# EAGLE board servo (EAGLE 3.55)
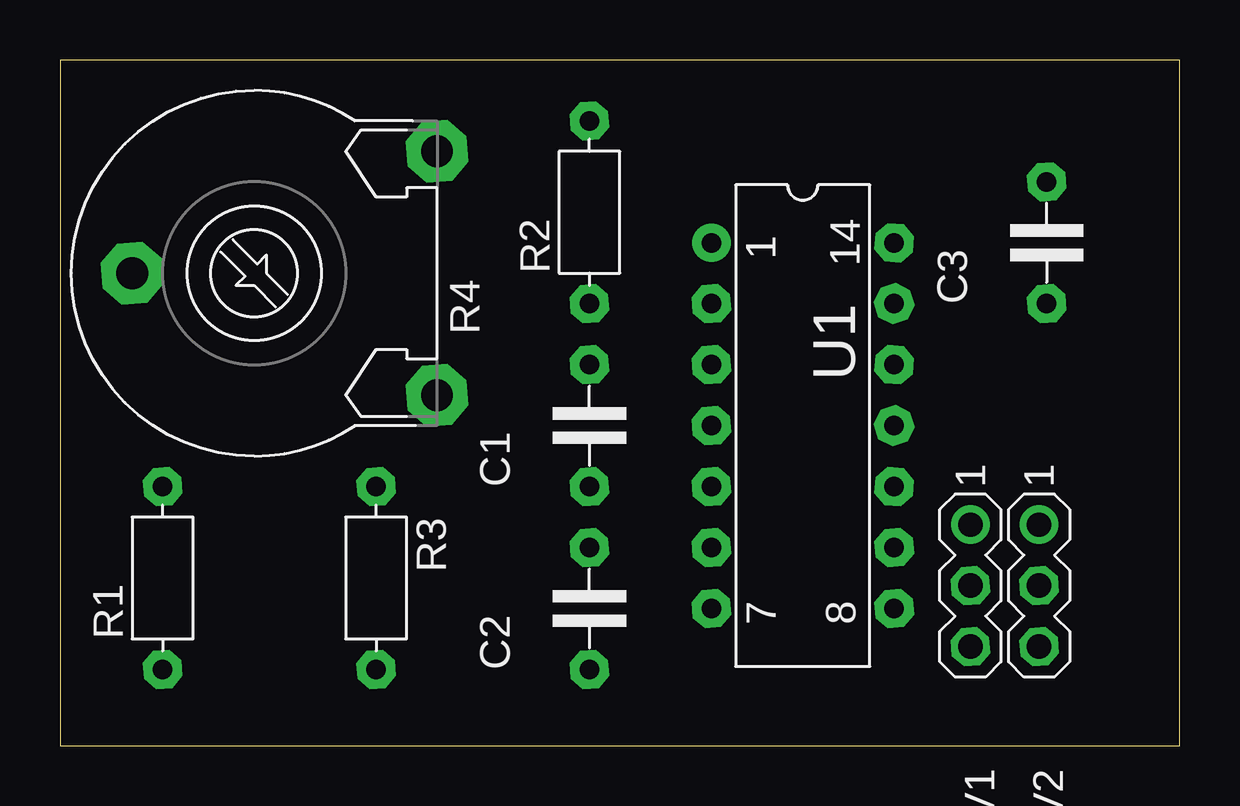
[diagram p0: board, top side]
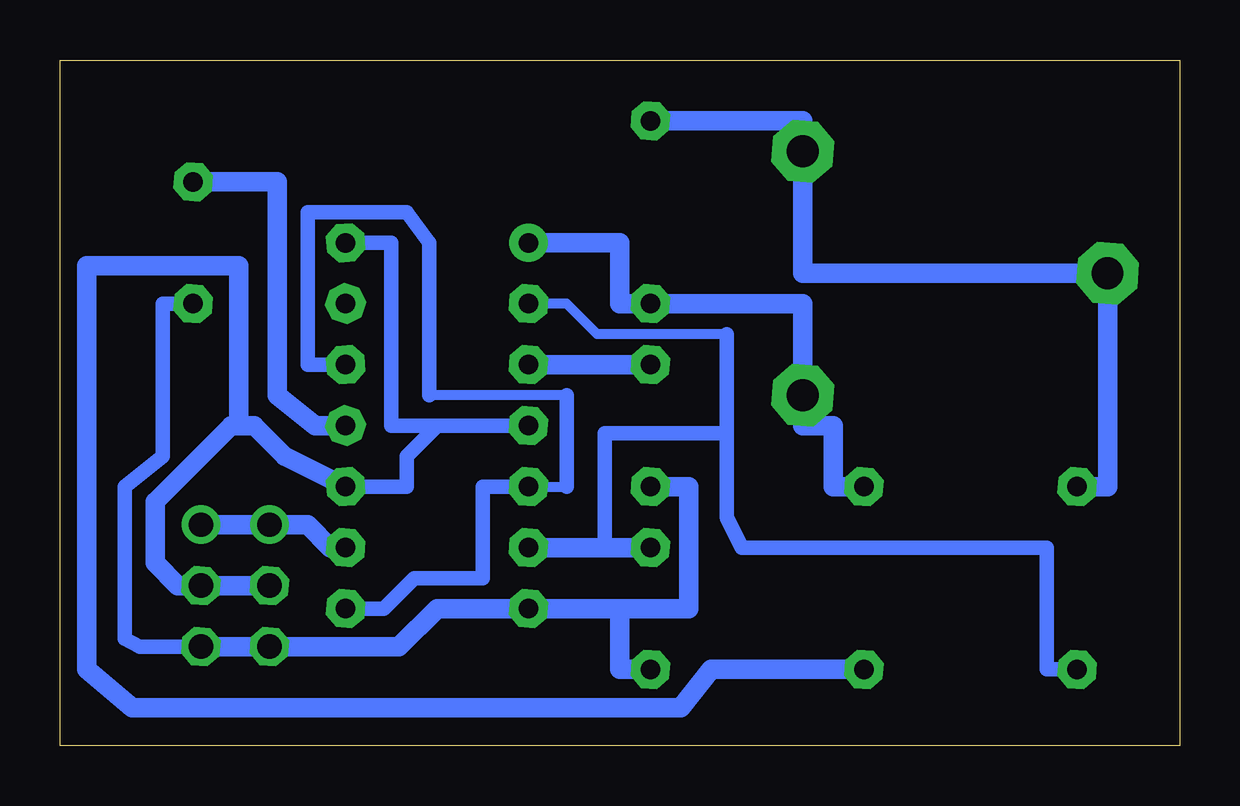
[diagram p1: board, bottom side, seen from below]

Size 46.66 x 28.56 mm. Coordinates in mm from the lower left corner, seen from the top.
Outline: 0,0 46.66,0 46.66,28.56 0,28.56 0,0
Copper layers used: Bottom

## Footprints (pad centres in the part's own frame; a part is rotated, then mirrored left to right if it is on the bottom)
5 = drill 0.813 pad 1.6 octagon:  -2.54,0;  2.54,0
7,5 = drill 0.813 pad 1.6 octagon:  -3.81,0;  3.81,0
15 = drill 1.321 pad 2.54 octagon:  -5.08,-7.62;  0,5.08;  5.08,-7.62
03-1 = drill 1.016 pad 1.6 round:  -2.54,0 | drill 1.016 pad 1.6 octagon:  0,0;  2.54,0
L14 = drill 0.813 pad 1.6 round:  -7.62,-3.81 | drill 0.813 pad 1.6 octagon:  -5.08,-3.81;  -2.54,-3.81;  0,-3.81;  2.54,-3.81;  5.08,-3.81;  7.62,-3.81;  7.62,3.81;  5.08,3.81;  2.54,3.81;  0,3.81;  -2.54,3.81;  -5.08,3.81;  -7.62,3.81

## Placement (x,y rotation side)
C1  47n  [5]  22.06,13.33 90 top
C2  330n  [5]  22.06,5.71 90 top
C3  47n  [5]  41.11,20.95 90 top
R1  4k  [7,5]  4.28,6.98 90 top
R2  10k  [7,5]  22.06,22.22 90 top
R3  47k  [7,5]  13.17,6.98 270 top
R4  5k  [15]  8.09,19.68 90 top
SV1  MA03-1  [03-1]  37.94,6.66 270 top
SV2  MA03-1  [03-1]  40.79,6.66 270 top
U1  556N  [L14]  30.95,13.33 270 top

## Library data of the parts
C1-C3 R1-R3 = DISCRETE
R4 = TRIMPOT
SV1 SV2 = CON-LSTB
U1 = LINEAR

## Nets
+5V: R3. SV1. SV2. U1.
GND: C1. C2. C3. SV1. SV2. U1.
N$1: C2. R1. U1.
N$2: C3. U1.
N$3: U1.
N$4: R2. R3. R4. U1.
N$5: C1. U1.
N$7: SV1. SV2. U1.
N$8: R1. R2. R4.

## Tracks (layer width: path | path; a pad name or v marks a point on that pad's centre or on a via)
+5V
  Bottom 0.61: 30.95,13.33 27.14,13.33 | 30.95,13.33 32.22,12.06 32.22,10.79 34.76,10.79 | U1. 32.86,20.95 32.86,13.33 30.95,13.33
  Bottom 0.813: R3. 19.52,3.17 20.79,1.58 43.65,1.58 45.56,3.17 45.56,20 39.2,20 39.2,13.33 | 39.2,13.33 39.52,13.33 42.7,10.16 42.7,7.61 41.75,6.66 40.79,6.66 37.94,6.66 | 39.2,13.33 38.57,13.33 37.3,12.06 34.76,10.79
GND
  Bottom 0.406: SV1. 38.25,4.12
  Bottom 0.61: 41.11,18.41 42.38,18.41 42.38,12.06 43.97,10.79 43.97,4.44 43.33,4.12 SV2.
  Bottom 0.813: 22.06,3.17 23.33,3.17 23.33,5.71 | 23.33,5.71 27.14,5.71 30.95,5.71 32.54,4.12 SV1. SV2. | 22.06,10.79 20.47,10.79 20.47,5.71 23.33,5.71
N$1
  Bottom 0.406: 27.14,18.41 25.55,18.41 24.28,17.14 18.89,17.14
  Bottom 0.61: 4.28,3.17 5.55,3.17 5.55,8.25 18.25,8.25 18.89,9.52 18.89,13.01 | 18.89,13.01 23.96,13.01 23.96,8.25 | 18.89,13.01 18.89,17.14
  Bottom 0.813: C2. 23.96,8.25 27.14,8.25
N$2
  Bottom 0.813: 34.76,13.33 36.03,13.33 37.62,14.6 37.62,23.49 C3.
N$3
  Bottom 0.406: 25.55,14.6 31.27,14.6 | 27.14,10.79 25.55,10.79
  Bottom 0.61: 27.14,10.79 29.04,10.79 29.04,6.98 31.9,6.98 33.17,5.71 34.76,5.71 | 34.76,15.87 36.35,15.87 36.35,22.22 32.22,22.22 31.27,20.95 31.27,14.6 | 25.55,10.79 25.55,14.6
N$4
  Bottom 0.406: 15.71,13.33 15.71,14.6
  Bottom 0.813: 13.17,10.79 14.44,10.79 14.44,13.33 15.71,13.33 | 27.14,20.95 23.33,20.95 23.33,18.41 22.06,18.41 15.71,18.41 15.71,14.6
N$5
  Bottom 0.813: C1. 27.14,15.87
N$7
  Bottom 0.813: 34.76,8.25 35.39,8.25 36.35,9.2 37.94,9.2 40.79,9.2
N$8
  Bottom 0.813: R2. 15.71,26.03 R4. 15.71,19.68 3.01,19.68 3.01,10.79 R1.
